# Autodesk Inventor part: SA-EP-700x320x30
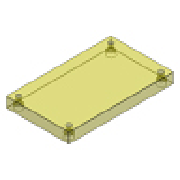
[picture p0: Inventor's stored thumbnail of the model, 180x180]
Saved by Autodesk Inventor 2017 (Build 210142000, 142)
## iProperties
Created: 2016-02
Part Number: SA-EP-700x320x30
Material: S 55 C
Description: Ejector Plate
Document SubType Name: Modeling
Designer: Sandeep
Standard Revision: 1
Manufacturer: FUTABA
Language: en-US
Size Designation: 700x320x30
Categories: <MemberInstance><Categories><Category DisplayName="Mold" InternalName="349578f2-f4d4-4954-8c09-8e99297a61c0" Mnemonic="MOLD"><Category DisplayName="Mold Plates"
Density: 7.85 g/cm^3
Appearance: Clear - Yellow
IsCustomPart: 1
Author: Sandeep
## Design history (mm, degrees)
sketch "Sketch1"
  geometry: L1 (-160, 350)-(160, 350); L2 (160, 350)-(160, -350); L3 (160, -350)-(-160, -350); L4 (-160, -350)-(-160, 350); 4 further points
  constraints: 8 end point, 2 midpoint, 2 parallel, 1 horizontal, 1 horizontal alignment, 1 perpendicular, 1 vertical alignment
  dimensions: "d74" = 147 horizontal distance of point (0, 0) point (-147, 337) (= 0.5 x S2_W); "d75" = 337 vertical distance of point (0, 0) point (-147, 337) (= 0.5 x S2_L); "d92" = 320 distance between parallel lines of L2 L4 (= W_); "d93" = 700 distance between parallel lines of L3 L1 (= L)
extrude "Extrusion1" new body sketch "Sketch1" distance "d20" = 30 (= H_); taper "d30" = 0 deg
body "Solid1"
hole "Hole1" sketch "Sketch1" diameter "d76" = 14 (= S2_d1); stored, may be unused: countersink angle "d80" = 90 deg, drill point angle "d82" = 0 deg; dims "d77" = 6, "d78" = 20 (= S2_d2), "d79" = 13 (= S2_k), "d81" = 30 (= H_)
pattern_linear "Rectangular Pattern1" dims "d85" = 674 (computed from S2_L, Nl), "d88" = 294 (computed from S2_W, Nw)
chamfer "Chamfer1" distance "d89" = 0.5; stored, may be unused: second distance "d90" = 2, angle "d91" = 45 deg
other parameters: "L" = 700 [user parameter; used in 1 equation term], "W_" = 320 [user parameter; used in 1 equation term], "H_" = 30 [user parameter; used in 2 equation terms], "S2_W" = 294 [user parameter; used in 2 equation terms], "S2_d1" = 14 [user parameter; used in 1 equation term], "S2_d2" = 20 [user parameter; used in 1 equation term], "S2_k" = 13 [user parameter; used in 1 equation term], "S2_L" = 674 [user parameter; used in 2 equation terms]
